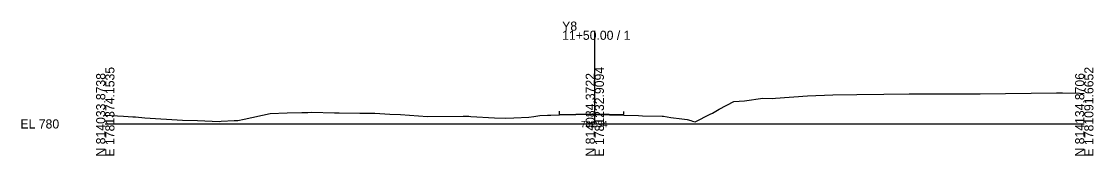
# Model space of a CAD drawing. Extents: x -26 to 303, y -10 to 5036.
# Drawn here: x -25.7 to 302.8, y 1990.3 to 2031.4 of the extents above; entities that cross this region are included whole.
import ezdxf

# ---------------------------------------------------------------- set-up
doc = ezdxf.new("R2010")
doc.units = 0
for name, color, linetype in [('Exist Cross Section Cell', 7, 'Continuous'), ('Exist XS Center Line Elevation Label', 7, 'Continuous'), ('Exist XS Ground Line', 7, 'Continuous'), ('Prop XS EOT Tick Mark', 7, 'Continuous'), ('Prop XS Finish Grade Pavement', 7, 'Continuous')]:
    doc.layers.add(name, color=color, linetype=linetype)

msp = doc.modelspace()

# ---------------------------------------------------------------- linework, layer by layer
at = {"layer": 'Exist Cross Section Cell'}
for p, q in [((150, 2000), (150, 2028.58)), ((0, 2000), (150, 2000)), ((150, 2000), (300, 2000))]:
    msp.add_line(p, q, dxfattribs=at)
at = {"layer": 'Exist XS Ground Line'}
for p, q in [((195.85, 2007.13), (201.5, 2007.85)), ((201.5, 2007.85), (204.39, 2007.82)), ((204.39, 2007.82), (205.4, 2007.86)), ((205.4, 2007.86), (215.18, 2008.59)), ((215.18, 2008.59), (222.94, 2008.88)), ((222.94, 2008.88), (230.29, 2009.01)), ((230.29, 2009.01), (238.59, 2009.14)), ((238.59, 2009.14), (246.36, 2009.22)), ((246.36, 2009.22), (250.4, 2009.26)), ((250.4, 2009.26), (253.59, 2009.24)), ((253.59, 2009.24), (268.05, 2009.27)), ((268.05, 2009.27), (291.51, 2009.5)), ((291.51, 2009.5), (293.32, 2009.53)), ((293.32, 2009.53), (298.56, 2009.46)), ((298.56, 2009.46), (300, 2009.35)), ((186.06, 2003.33), (188.14, 2004.49)), ((188.14, 2004.49), (192.58, 2006.83)), ((192.58, 2006.83), (195.85, 2007.13)), ((0, 2002.66), (5.62, 2002.34)), ((5.62, 2002.34), (8.49, 2002.17)), ((8.49, 2002.17), (9.29, 2002.13)), ((9.29, 2002.13), (12.16, 2001.92)), ((12.16, 2001.92), (23.61, 2001.17)), ((23.61, 2001.17), (28.3, 2001.04)), ((28.3, 2001.04), (35.04, 2000.78)), ((35.04, 2000.78), (35.47, 2000.82)), ((35.47, 2000.82), (39.47, 2001.06)), ((39.47, 2001.06), (40.66, 2001.03)), ((40.66, 2001.03), (42.56, 2001.42)), ((42.56, 2001.42), (50.48, 2003.2)), ((50.48, 2003.2), (55.76, 2003.37)), ((55.76, 2003.37), (60.2, 2003.54)), ((60.2, 2003.54), (62.11, 2003.55)), ((62.11, 2003.55), (63.19, 2003.58)), ((63.19, 2003.58), (70.22, 2003.41)), ((70.22, 2003.41), (71.66, 2003.41)), ((71.66, 2003.41), (78.02, 2003.34)), ((78.02, 2003.34), (80.12, 2003.33)), ((80.12, 2003.33), (82.58, 2003.27)), ((82.58, 2003.27), (87.23, 2003.04)), ((87.23, 2003.04), (90.48, 2002.87)), ((90.48, 2002.87), (95.93, 2002.46)), ((95.93, 2002.46), (98.75, 2002.24)), ((98.75, 2002.24), (109.66, 2002.36)), ((109.66, 2002.36), (111.37, 2002.36)), ((111.37, 2002.36), (112.01, 2002.33)), ((112.01, 2002.33), (119.25, 2001.9)), ((119.25, 2001.9), (122.62, 2001.73)), ((122.62, 2001.73), (125.2, 2001.87)), ((125.2, 2001.87), (129.78, 2002.04)), ((129.78, 2002.04), (131.36, 2002.3)), ((131.36, 2002.3), (133.19, 2002.57)), ((133.19, 2002.57), (135.55, 2002.67)), ((135.55, 2002.67), (136.51, 2002.7)), ((136.51, 2002.7), (139.17, 2002.76)), ((139.17, 2002.76), (149.19, 2002.96)), ((149.19, 2002.96), (150, 2002.94)), ((150, 2002.94), (158.93, 2002.73)), ((158.93, 2002.73), (163.42, 2002.62)), ((163.42, 2002.62), (164.57, 2002.51)), ((164.57, 2002.51), (170.64, 2002.42)), ((170.64, 2002.42), (171.1, 2002.41)), ((171.1, 2002.41), (173.34, 2001.99)), ((173.34, 2001.99), (176.71, 2001.53)), ((176.71, 2001.53), (178.26, 2001.33)), ((178.26, 2001.33), (179.41, 2001.1)), ((179.41, 2001.1), (179.92, 2000.87)), ((179.92, 2000.87), (180.74, 2000.66)), ((180.74, 2000.66), (185.31, 2003)), ((185.31, 2003), (186.06, 2003.33))]:
    msp.add_line(p, q, dxfattribs=at)
at = {"layer": 'Prop XS EOT Tick Mark'}
for p, q in [((139.17, 2002.89), (139.17, 2003.89)), ((158.93, 2002.86), (158.93, 2003.86))]:
    msp.add_line(p, q, dxfattribs=at)
at = {"layer": 'Prop XS Finish Grade Pavement'}
for p, q in [((139.17, 2002.89), (149.19, 2003.08)), ((149.19, 2003.08), (150, 2003.07)), ((150, 2003.07), (158.93, 2002.86))]:
    msp.add_line(p, q, dxfattribs=at)

# ---------------------------------------------------------------- texts
at = {"layer": 'Exist Cross Section Cell'}
for s, p in [('Y8', (140, 2028.58)), ('11+50.00 / 1', (140, 2025.78)), ('EL 780', (-26, 1998.6))]:
    msp.add_text(s, height=2.8, dxfattribs=at).set_placement(p)
for s, p in [('E 1781374.1535', (2.8, 1990)), ('E 1781232.9094', (152.8, 1990)), ('E 1781091.6652', (302.8, 1990)), ('N 814033.8738', (0, 1990)), ('N 814084.3722', (150, 1990)), ('N 814134.8706', (300, 1990))]:
    msp.add_text(s, height=2.8, rotation=90, dxfattribs=at).set_placement(p)
at = {"layer": 'Exist XS Center Line Elevation Label'}
msp.add_text('782.94', height=2, dxfattribs=at).set_placement((145.72, 1998.94))

doc.saveas('drawing.dxf')
